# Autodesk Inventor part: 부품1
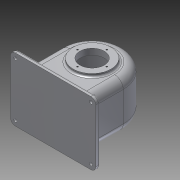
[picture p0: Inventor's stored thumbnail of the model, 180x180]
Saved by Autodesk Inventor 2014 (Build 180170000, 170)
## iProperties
Created: 2016-01
Part Number: 부품1
Material: 알루미늄 6061
Document SubType Name: Modeling
Designer: SEC
Density: 2.71 g/cm^3
Appearance: 알루미늄 - 평지
Mass: 1152.63 g
Surface Area: 939.431 cm^2
Volume: 425.326 cm^3
Author: SEC
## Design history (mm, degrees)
sketch "스케치2"
  geometry: L1 (51, -64)-(-51, -64); L2 (-51, -64)-(-51, 0); L3 (51, 0)-(51, -64); L4 (-51, 0)-(51, 0); A1 r 51 centre (0, 0) between (51, 0) and (-51, 0); 2 further points
  constraints: 8 end point, 2 coincident, 2 perpendicular, 2 point on circle, 1 centre point, 1 horizontal, 1 parallel
  dimensions: "d26" = 51 radius of A1; "d27" = 64 distance of L1.end L2.end; "d28" = 102 distance of L1.start L1.end
extrude "돌출1" new body sketch "스케치2" stored distance "d3" = 77; taper "d4" = 0 deg
sketch "스케치3"
  geometry: C1 r 31 at (0, 0); A1 r 51 centre (0, 0) between (51, 0) and (-51, 0) reference
  constraints: 1 centre point, 1 coincident
  dimensions: "d5" = 62 diameter of C1
extrude "돌출2" join sketch "스케치3" distance "d6" = 5; taper "d7" = 0 deg
sketch "스케치4"
  geometry: L1 (102, 0)-(102, -77) reference; L2 (0, 0)-(102, 0) reference; L3 (0, -77)-(0, 0) reference; L4 (102, -77)-(0, -77) reference; L5 (121, -90.5)-(-19, -90.5); L6 (-19, -90.5)-(-19, 13.5); L7 (-19, 13.5)-(121, 13.5); L8 (121, 13.5)-(121, -90.5); L9 (-19, -90.5)-(121, 13.5); 2 further points
  constraints: 10 end point, 2 parallel, 1 coincident, 1 horizontal, 1 midpoint, 1 perpendicular
  dimensions: "d8" = 104 distance of L5.end L6.end; "d9" = 140 distance of L6.end L7.end
extrude "돌출3" join sketch "스케치4" distance "d10" = 7; taper "d11" = 0 deg
fillet "모깎기1" dims "d13" = 8
sketch "스케치7"
  geometry: 6 further points
  constraints: 1 other
hole "구멍1" sketch "스케치7" at (-11, 5.5) diameter "d14" = 5; stored, may be unused: countersink angle "d18" = 90 deg, drill point angle "d20" = 118 deg; dims "d15" = 6, "d16" = 4, "d17" = 2, "d19" = 8
node "작업 평면3"
sketch "스케치12"
  geometry: L1 (-51, -57)-(51, -57) reference; L2 (51, -57)-(51, 0) reference; L3 (-51, 0)-(-51, -57) reference; A1 r 51 centre (0, 0) between (51, 0) and (-51, 0) reference
sketch "스케치13"
  geometry: L1 (46, -33.5)-(46, 33.5); L2 (46, 33.5)-(20, 33.5); L3 (46, -33.5)-(39.747, -33.5); L4 (39.747, -33.5)-(28, -19.5); L5 (28, -19.5)-(20, -19.5); L6 (0, 38.5)-(0, -38.5) reference; L7 (0, -38.5)-(51, -38.5) reference; L8 (0, 38.5)-(0, -38.5) reference; L9 (0, 38.5)-(0, 38.5) reference; L10 (0, -38.5)-(0, 38.5) reference; L11 (0, -38.5)-(0, -38.5) reference; L12 (51, -38.5)-(51, 38.5) reference; L13 (51, 38.5)-(0, 38.5) reference; L14 (31, 43.5)-(-31, 43.5) reference; L15 (0, -38.5)-(20, -38.5); L16 (20, 33.5)-(20, -19.5); 1 further point
  constraints: 14 end point, 2 perpendicular, 1 parallel, 1 point on line, 1 vertical
  dimensions: "d36" = 28 distance from line of L6 L4.end; "d37" = 5 distance between parallel lines of L7 L3; "d38" = 50 deg angle of L5 L4; "d39" = 5 distance between parallel lines of L1 L12; "d40" = 5 distance between parallel lines of L13 L2; "d42" = 19 distance between parallel lines of L7 L5; "d59" = 20 distance between parallel lines of L6 L16
  node "투영된 루프1"
sketch "스케치14"
  geometry: C1 r 31 at (0, 0) reference; C2 r 20 at (0, 0)
  constraints: 1 centre point, 1 coincident
  dimensions: "d45" = 40 diameter of C2
extrude "돌출6" cut sketch "스케치14" stored distance "d46" = 7; taper "d47" = 0 deg
sketch "스케치15" dims "d48" = 48
  geometry: C1 r 20 at (0, 0) reference; 2 further points
  constraints: 2 vertical alignment, 1 coincident, 2 other
hole "구멍2" sketch "스케치15" at (0, 24) diameter "d49" = 2.459; stored, may be unused: countersink angle "d53" = 90 deg, drill point angle "d55" = 118 deg; dims "d50" = 6, "d51" = 4, "d52" = 2, "d54" = 8
revolve "회전1" stored, may be unused: angle "d60" = 90 deg
sketch "스케치17"
  geometry: L1 (0, -57)-(77, -57) reference; L2 (77, 0)-(77, -57) reference; L3 (77, 0)-(0, 0) reference; L4 (0, -57)-(0, 0) reference; 1 further point
sketch "스케치19"
  geometry: L1 (0, -38.5)-(51, -38.5) reference; L2 (39.747, -33.5)-(28, -19.5) reference; L3 (37.416, -38.5)-(34.899, -35.5); L4 (34.899, -35.5)-(20, -35.5); L5 (20, -19.5)-(20, -38.5) reference; L6 (20, -35.5)-(20, -38.5); L7 (0, -72.8)-(0, 72.8) reference; 1 further point
  constraints: 6 end point, 2 parallel, 1 collinear, 1 point on line
  dimensions: "d74" = 5 distance between parallel lines of L2 L3; "d76" = 3 vertical distance of L3.end L3.start
revolve "회전2" sketch "스케치19" stored, may be unused: angle "d77" = 90 deg
sketch "스케치20" dims "d80" = 56
  geometry: C1 r 39.747 at (0, 0) reference; 2 further points
  constraints: 2 vertical alignment, 1 coincident, 2 other
hole "구멍4" sketch "스케치20" at (0, 28) diameter "d81" = 2.459; stored, may be unused: countersink angle "d85" = 90 deg, drill point angle "d87" = 118 deg; dims "d82" = 7, "d83" = 4, "d84" = 2, "d86" = 9
fillet "모깎기2" dims "d100" = 14
fillet "모깎기3" dims "d101" = 9
fillet "모깎기4" dims "d102" = 3
fillet "모깎기5" dims "d103" = 3
sketch "스케치25"
  geometry: 1 further point
sketch "스케치26"
  geometry: 1 further point
node "작업 평면6"
sketch "스케치27"
  geometry: C1 r 6 at (0, 0); 1 further point
  constraints: 1 centre point, 1 coincident
  dimensions: "d107" = 12 diameter of C1
extrude "돌출8" join sketch "스케치27" stored distance "d108" = 7; taper "d109" = 0 deg
hole "구멍6" diameter "d112" = 4.459; stored, may be unused: countersink angle "d116" = 90 deg, drill point angle "d118" = 0 deg; dims "d110" = 10, "d111" = 10, "d113" = 7, "d114" = 4, "d115" = 2, "d117" = 6
sketch "스케치28"
  geometry: L1 (-68.5, -7)-(19.5, -7) reference; L2 (-63, 51.437)-(-63, 0) reference; 2 further points
  constraints: 1 other
  dimensions: "d119" = 30 distance from line of L1 point (-24.5, 23); "d120" = 38.5 distance from line of L2 point (-24.5, 23)
feature "엠보싱1" sketch "스케치28" dims "d26" = 51, "d27" = 64, "d28" = 102, "d121" = 0.5, "d122" = 0
fillet "모깎기6" dims "d123" = 3
node "솔리드1"
mirror "대칭1"
mirror "대칭2"
pattern_circular "원형 패턴1" dims angle "d57" = 360 deg
pattern_circular "원형 패턴3" dims angle "d89" = 360 deg
other parameters: "d30" = 63, "d106" = 57
